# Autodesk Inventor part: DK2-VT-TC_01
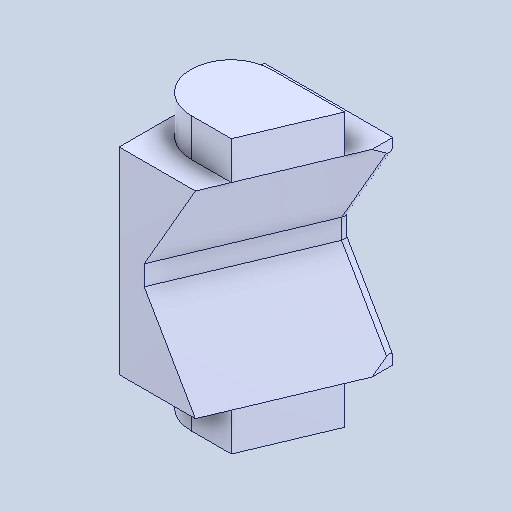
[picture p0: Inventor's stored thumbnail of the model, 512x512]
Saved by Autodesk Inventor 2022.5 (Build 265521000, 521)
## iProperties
Created: 2024-05
Part Number: DK2-VT-TC_01
Material: 一般
Document SubType Name: Modeling
Designer: ImaoCorp
Density: 1 g/cm^3
Appearance: 既定
Author: ImaoCorp
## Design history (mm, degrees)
feature "DK2-VT-TC_01"
node "ソリッド1"
